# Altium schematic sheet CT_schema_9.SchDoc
size 254 x 194 mm
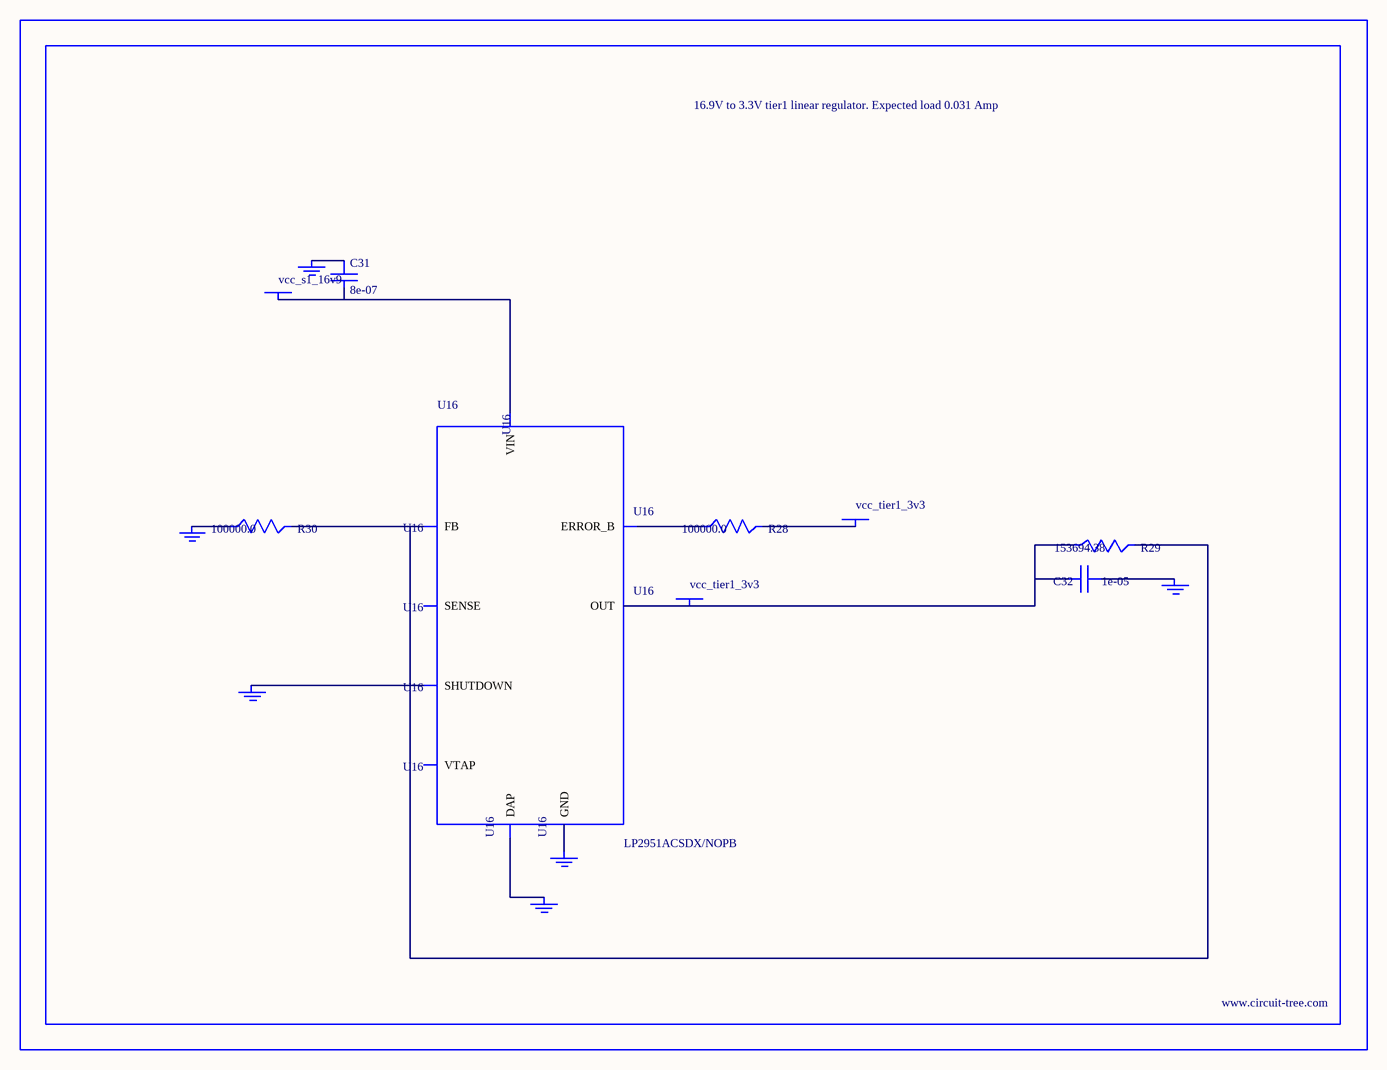
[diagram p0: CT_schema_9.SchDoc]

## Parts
BORDER8  (no value)
C31  8e-07  [R0603]
C32  1e-05  [C1210]
GND_INSTANCE_8_0  (no value)
GND_INSTANCE_8_1  (no value)
GND_INSTANCE_8_2  (no value)
GND_INSTANCE_8_3  (no value)
GND_INSTANCE_8_4  (no value)
GND_INSTANCE_8_5  (no value)
POWER_INSTANCE_8_0  vcc_tier1_3v3
POWER_INSTANCE_8_1  vcc_s1_16v9
POWER_INSTANCE_8_2  vcc_tier1_3v3
R28  100000.0  [R0603]
R29  153694.38  [R0603]
R30  100000.0  [R0603]
U16  LP2951ACSDX/NOPB  [WSON-8]

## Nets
NetC31_1: C31.1 GND_INSTANCE_8_3.0(GND)
NetC31_2: C31.2 POWER_INSTANCE_8_1.0(PWR) U16.8(VIN)
NetC32_1: C32.1 GND_INSTANCE_8_0.0(GND)
NetC32_2: C32.2 POWER_INSTANCE_8_2.0(PWR) R29.1 U16.1(OUT)
NetGND_INSTANCE_8_1_0: GND_INSTANCE_8_1.0(GND) U16.3(SHUTDOWN)
NetGND_INSTANCE_8_2_0: GND_INSTANCE_8_2.0(GND) R30.1
NetGND_INSTANCE_8_4_0: GND_INSTANCE_8_4.0(GND) U16.PAD(DAP)
NetGND_INSTANCE_8_5_0: GND_INSTANCE_8_5.0(GND) U16.4(GND)
NetPOWER_INSTANCE_8_0_0: POWER_INSTANCE_8_0.0(PWR) R28.2
NetR28_1: R28.1 U16.5(ERROR_B)
NetR29_2: R29.2 R30.2 U16.7(FB)

Not connected (* = marked no-connect by the designer): U16 2(SENSE) 6(VTAP)

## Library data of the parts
BORDER8 = BORDER_PAGE8
C31 = C31
C32 = GRM32DR61E106MA12L
GND_INSTANCE_8_0-GND_INSTANCE_8_5 = GND
POWER_INSTANCE_8_0-POWER_INSTANCE_8_2 = PWR
R28 R30 = RC0603JR-07100KL
R29 = R29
